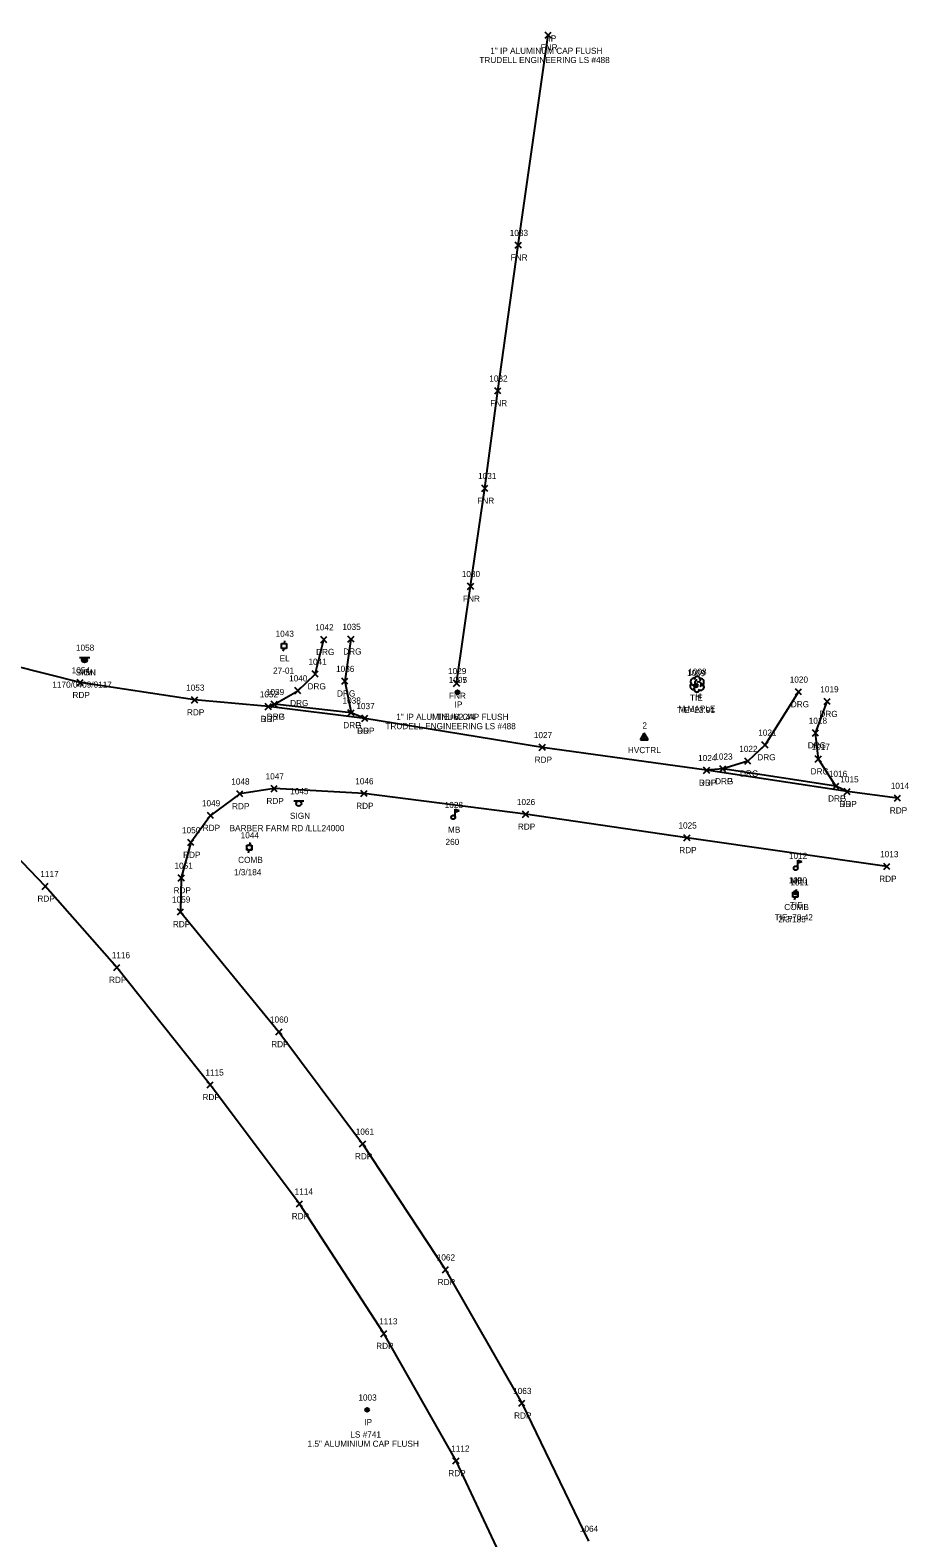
# Model space of a CAD drawing. Extents: x 1503463 to 1505240, y 712171 to 717196.
# Drawn here: x 1504897.3 to 1505182.8, y 713821.7 to 714311.7 of the extents above; entities that cross this region are included whole.
import ezdxf

# ---------------------------------------------------------------- set-up
doc = ezdxf.new("R2010")
doc.units = 0
for name, color, linetype in [('C_A', 7, 'Continuous'), ('C_C', 7, 'Continuous'), ('C_I', 7, 'Continuous'), ('CBP', 7, 'Continuous'), ('CPSM', 7, 'Continuous'), ('L_A', 7, 'Continuous'), ('L_C', 7, 'Continuous'), ('L_I', 7, 'Continuous'), ('L_TIC', 7, 'Continuous'), ('LFNC', 7, 'Continuous'), ('LMB', 7, 'Continuous'), ('LTD', 7, 'Continuous'), ('M_A', 7, 'Continuous'), ('M_C', 7, 'Continuous'), ('M_I', 7, 'Continuous'), ('MPIR', 7, 'Continuous'), ('P_A', 7, 'Continuous'), ('P_I', 7, 'Continuous'), ('P_TIC', 7, 'Continuous'), ('PET', 7, 'Continuous'), ('R_A', 7, 'Continuous'), ('R_I', 7, 'Continuous'), ('R_TIC', 7, 'Continuous'), ('RDG', 7, 'Continuous'), ('RDP', 7, 'Continuous'), ('S_A', 7, 'Continuous'), ('S_C', 7, 'Continuous'), ('S_I', 7, 'Continuous'), ('SRM', 7, 'Continuous'), ('SSGN', 7, 'Continuous'), ('U_A', 7, 'Continuous'), ('U_C', 7, 'Continuous'), ('U_I', 7, 'Continuous'), ('UEPT', 7, 'Continuous'), ('UP', 7, 'Continuous')]:
    doc.layers.add(name, color=color, linetype=linetype)

msp = doc.modelspace()

# ---------------------------------------------------------------- linework, layer by layer
at = {"layer": 'CBP'}
for centre, radius in [((1505113.6, 714098.77), 0.625), ((1505113.6, 714098.77), 0.0833), ((1505146.06, 714031.41), 0.625), ((1505146.06, 714031.41), 0.0833)]:
    msp.add_circle(centre, radius, dxfattribs=at)
at = {"layer": 'CPSM'}
for p, q in [((1505095.56, 714081.03), (1505096.81, 714083.19)), ((1505095.56, 714081.03), (1505096.81, 714081.75)), ((1505095.56, 714081.03), (1505098.06, 714081.03)), ((1505098.06, 714081.03), (1505096.81, 714083.19)), ((1505096.81, 714081.75), (1505096.81, 714083.19)), ((1505096.81, 714081.75), (1505096.81, 714081.75)), ((1505096.81, 714081.75), (1505098.06, 714081.03))]:
    msp.add_line(p, q, dxfattribs=at)
at = {"layer": 'L_TIC'}
for points in [[(1505064.62, 714309.08), (1505066.62, 714311.08)], [(1505066.62, 714309.08), (1505064.62, 714311.08)], [(1505054.9, 714240.8), (1505056.9, 714242.8)], [(1505056.9, 714240.8), (1505054.9, 714242.8)], [(1505048.26, 714193.47), (1505050.26, 714195.47)], [(1505050.26, 714193.47), (1505048.26, 714195.47)], [(1505044.04, 714161.81), (1505046.04, 714163.81)], [(1505046.04, 714161.81), (1505044.04, 714163.81)], [(1505039.41, 714129.96), (1505041.41, 714131.96)], [(1505041.41, 714129.96), (1505039.41, 714131.96)], [(1505034.86, 714098.43), (1505036.86, 714100.43)], [(1505036.86, 714098.43), (1505034.86, 714100.43)]]:
    msp.add_lwpolyline(points, dxfattribs=at)
at = {"layer": 'LFNC'}
msp.add_lwpolyline([(1505035.86, 714099.43), (1505040.41, 714130.96), (1505045.04, 714162.81), (1505049.26, 714194.47), (1505055.9, 714241.8), (1505065.62, 714310.08)], dxfattribs=at)
at = {"layer": 'LMB'}
for p, q in [((1505034.76, 714055.9), (1505034.76, 714055.9)), ((1505035.41, 714058.5), (1505036.7, 714058.12)), ((1505035.41, 714055.91), (1505035.41, 714058.5)), ((1505035.41, 714057.6), (1505036.69, 714058.11)), ((1505146.69, 714041.97), (1505147.98, 714041.58)), ((1505146.7, 714039.37), (1505146.7, 714041.97)), ((1505146.7, 714041.07), (1505147.98, 714041.58)), ((1505146.04, 714039.37), (1505146.04, 714039.37))]:
    msp.add_line(p, q, dxfattribs=at)
for centre in [(1505034.76, 714055.9), (1505146.04, 714039.37)]:
    msp.add_circle(centre, 0.656, dxfattribs=at)
at = {"layer": 'LTD'}
msp.add_line((1505113.98, 714099.22), (1505113.98, 714099.22), dxfattribs=at)
msp.add_line((1505113.98, 714099.22), (1505113.98, 714099.22), dxfattribs=at)
msp.add_arc((1505114.02, 714100.65), 1.05, 335.5272, 180.9563, dxfattribs=at)
for centre, major_axis, ratio, start_param, end_param in [((1505112.89, 714098.51), (0.58, -1.04), 0.959034, 3.141593, 6.283185), ((1505113.18, 714099.89), (1.21, -0.51), 0.895232, 1.570796, 4.712389), ((1505113.77, 714099.68), (-0.208, -0.792), 0.645439, 3.141593, 6.283185), ((1505114.48, 714099.05), (-0.5, 0.667), 0.989748, 3.141593, 6.283185), ((1505114.98, 714098.39), (-1.09, 0.79), 0.841452, 1.570796, 4.712389), ((1505115.02, 714099.8), (-1.14, -0.48), 0.949671, 1.570796, 4.712389), ((1505113.98, 714097.72), (0.26, 1.06), 0.942809, 1.570796, 4.712389), ((1505113.52, 714098.47), (-0.625, -0.083), 0.423636, 0, 3.141593)]:
    msp.add_ellipse(centre, major_axis=major_axis, ratio=ratio, start_param=start_param, end_param=end_param, dxfattribs=at)
at = {"layer": 'MPIR'}
for centre, radius in [((1505036.16, 714096.53), 0.625), ((1505036.17, 714096.54), 0.625), ((1505036.16, 714096.53), 0.0833), ((1505036.17, 714096.54), 0.0833), ((1505006.82, 713863.34), 0.625), ((1505006.82, 713863.34), 0.0833)]:
    msp.add_circle(centre, radius, dxfattribs=at)
at = {"layer": 'P_TIC'}
for points in [[(1504912.58, 714098.65), (1504914.58, 714100.65)], [(1504914.58, 714098.65), (1504912.58, 714100.65)], [(1504949.76, 714093.03), (1504951.76, 714095.03)], [(1504951.76, 714093.03), (1504949.76, 714095.03)], [(1504973.7, 714090.87), (1504975.7, 714092.87)], [(1504975.7, 714090.87), (1504973.7, 714092.87)], [(1505005.07, 714087.04), (1505007.07, 714089.04)], [(1505007.07, 714087.04), (1505005.07, 714089.04)], [(1505062.73, 714077.62), (1505064.73, 714079.62)], [(1505064.73, 714077.62), (1505062.73, 714079.62)], [(1505116.1, 714070.16), (1505118.1, 714072.16)], [(1505118.1, 714070.16), (1505116.1, 714072.16)], [(1504964.42, 714062.52), (1504966.42, 714064.52)], [(1504966.42, 714062.52), (1504964.42, 714064.52)], [(1504975.58, 714064.21), (1504977.58, 714066.21)], [(1504977.58, 714064.21), (1504975.58, 714066.21)], [(1505004.76, 714062.62), (1505006.76, 714064.62)], [(1505006.76, 714062.62), (1505004.76, 714064.62)], [(1505161.73, 714063.23), (1505163.73, 714065.23)], [(1505163.73, 714063.23), (1505161.73, 714065.23)], [(1505178.12, 714061.13), (1505180.12, 714063.13)], [(1505180.12, 714061.13), (1505178.12, 714063.13)], [(1504954.89, 714055.47), (1504956.89, 714057.47)], [(1504956.89, 714055.47), (1504954.89, 714057.47)], [(1505057.28, 714055.87), (1505059.28, 714057.87)], [(1505059.28, 714055.87), (1505057.28, 714057.87)], [(1505109.71, 714048.24), (1505111.71, 714050.24)], [(1505111.71, 714048.24), (1505109.71, 714050.24)], [(1504948.51, 714046.7), (1504950.51, 714048.7)], [(1504950.51, 714046.7), (1504948.51, 714048.7)], [(1505174.67, 714038.92), (1505176.67, 714040.92)], [(1505176.67, 714038.92), (1505174.67, 714040.92)], [(1504945.41, 714035.18), (1504947.41, 714037.18)], [(1504947.41, 714035.18), (1504945.41, 714037.18)], [(1504901.19, 714032.47), (1504903.19, 714034.47)], [(1504903.19, 714032.47), (1504901.19, 714034.47)], [(1504945.19, 714024.17), (1504947.19, 714026.17)], [(1504947.19, 714024.17), (1504945.19, 714026.17)], [(1504924.45, 714006.09), (1504926.45, 714008.09)], [(1504926.45, 714006.09), (1504924.45, 714008.09)], [(1504977.14, 713985.17), (1504979.14, 713987.17)], [(1504979.14, 713985.17), (1504977.14, 713987.17)], [(1504954.82, 713967.98), (1504956.82, 713969.98)], [(1504956.82, 713967.98), (1504954.82, 713969.98)], [(1505004.34, 713948.76), (1505006.34, 713950.76)], [(1505006.34, 713948.76), (1505004.34, 713950.76)], [(1504983.81, 713929.29), (1504985.81, 713931.29)], [(1504985.81, 713929.29), (1504983.81, 713931.29)], [(1505031.24, 713907.87), (1505033.24, 713909.87)], [(1505033.24, 713907.87), (1505031.24, 713909.87)], [(1505011.25, 713887.12), (1505013.25, 713889.12)], [(1505013.25, 713887.12), (1505011.25, 713889.12)], [(1505056.05, 713864.49), (1505058.05, 713866.49)], [(1505058.05, 713864.49), (1505056.05, 713866.49)], [(1505034.67, 713845.75), (1505036.67, 713847.75)], [(1505036.67, 713845.75), (1505034.67, 713847.75)]]:
    msp.add_lwpolyline(points, dxfattribs=at)
at = {"layer": 'PET'}
for points in [[(1505179.12, 714062.13), (1505162.73, 714064.23), (1505117.1, 714071.16), (1505063.73, 714078.62), (1505006.07, 714088.04), (1504974.7, 714091.87), (1504950.76, 714094.03), (1504913.58, 714099.65), (1504891.67, 714105.18), (1504874.38, 714111.13), (1504858.75, 714121.03), (1504839.76, 714141.64), (1504813.09, 714174.5), (1504792.31, 714203.38), (1504770.85, 714238.46), (1504747.85, 714282.15), (1504727.38, 714327.5), (1504712.05, 714367.82), (1504697.71, 714414.83), (1504685.11, 714458.97), (1504676.94, 714491.61), (1504665.42, 714541.32), (1504657.14, 714577.6), (1504649.31, 714613.48)], [(1505055.48, 713804.69), (1505035.67, 713846.75), (1505012.25, 713888.12), (1504984.81, 713930.29), (1504955.82, 713968.98), (1504925.45, 714007.09), (1504902.19, 714033.47), (1504875.2, 714061.56), (1504841.23, 714097.76), (1504824.92, 714116.29), (1504805.14, 714139.73), (1504789.93, 714158.37), (1504770.9, 714185.14), (1504747.1, 714223.61), (1504721.17, 714273.06), (1504701.58, 714317.3), (1504686.12, 714357.97), (1504670.15, 714407.6), (1504658, 714450.85), (1504649.24, 714485.62), (1504637.84, 714534.39), (1504628.86, 714571.69), (1504621.33, 714603.22)], [(1505175.67, 714039.92), (1505110.71, 714049.24), (1505058.28, 714056.87), (1505005.76, 714063.62), (1504976.58, 714065.21), (1504965.42, 714063.52), (1504955.89, 714056.47), (1504949.51, 714047.7), (1504946.41, 714036.18), (1504946.19, 714025.17), (1504978.14, 713986.17), (1505005.34, 713949.76), (1505032.24, 713908.87), (1505057.05, 713865.49), (1505078.73, 713820.71)]]:
    msp.add_lwpolyline(points, dxfattribs=at)
at = {"layer": 'R_TIC'}
for points in [[(1504991.72, 714112.64), (1504993.72, 714114.64)], [(1504993.72, 714112.64), (1504991.72, 714114.64)], [(1505000.54, 714112.78), (1505002.54, 714114.78)], [(1505002.54, 714112.78), (1505000.54, 714114.78)], [(1504988.94, 714101.45), (1504990.94, 714103.45)], [(1504990.94, 714101.45), (1504988.94, 714103.45)], [(1504998.54, 714099.14), (1505000.54, 714101.14)], [(1505000.54, 714099.14), (1504998.54, 714101.14)], [(1504983.3, 714096.04), (1504985.3, 714098.04)], [(1504985.3, 714096.04), (1504983.3, 714098.04)], [(1505145.95, 714095.65), (1505147.95, 714097.65)], [(1505147.95, 714095.65), (1505145.95, 714097.65)], [(1505155.24, 714092.5), (1505157.24, 714094.5)], [(1505157.24, 714092.5), (1505155.24, 714094.5)], [(1504973.7, 714090.87), (1504975.7, 714092.87)], [(1504975.7, 714090.87), (1504973.7, 714092.87)], [(1504975.67, 714091.61), (1504977.67, 714093.61)], [(1504977.67, 714091.61), (1504975.67, 714093.61)], [(1504975.67, 714091.61), (1504977.67, 714093.61)], [(1504977.67, 714091.61), (1504975.67, 714093.61)], [(1505000.57, 714088.84), (1505002.57, 714090.84)], [(1505002.57, 714088.84), (1505000.57, 714090.84)], [(1505000.57, 714088.84), (1505002.57, 714090.84)], [(1505002.57, 714088.84), (1505000.57, 714090.84)], [(1505005.07, 714087.04), (1505007.07, 714089.04)], [(1505007.07, 714087.04), (1505005.07, 714089.04)], [(1505151.47, 714082.29), (1505153.47, 714084.29)], [(1505153.47, 714082.29), (1505151.47, 714084.29)], [(1505135.07, 714078.41), (1505137.07, 714080.41)], [(1505137.07, 714078.41), (1505135.07, 714080.41)], [(1505129.46, 714073.13), (1505131.46, 714075.13)], [(1505131.46, 714073.13), (1505129.46, 714075.13)], [(1505152.4, 714073.82), (1505154.4, 714075.82)], [(1505154.4, 714073.82), (1505152.4, 714075.82)], [(1505116.1, 714070.16), (1505118.1, 714072.16)], [(1505118.1, 714070.16), (1505116.1, 714072.16)], [(1505121.36, 714070.64), (1505123.36, 714072.64)], [(1505123.36, 714070.64), (1505121.36, 714072.64)], [(1505121.36, 714070.64), (1505123.36, 714072.64)], [(1505123.36, 714070.64), (1505121.36, 714072.64)], [(1505158.06, 714065.02), (1505160.06, 714067.02)], [(1505160.06, 714065.02), (1505158.06, 714067.02)], [(1505158.06, 714065.02), (1505160.06, 714067.02)], [(1505160.06, 714065.02), (1505158.06, 714067.02)], [(1505161.73, 714063.23), (1505163.73, 714065.23)], [(1505163.73, 714063.23), (1505161.73, 714065.23)]]:
    msp.add_lwpolyline(points, dxfattribs=at)
at = {"layer": 'RDG'}
for points in [[(1504976.67, 714092.61), (1504984.3, 714097.04), (1504989.94, 714102.45), (1504992.72, 714113.64)], [(1505001.54, 714113.78), (1504999.54, 714100.14), (1505001.57, 714089.84)], [(1505146.95, 714096.65), (1505136.07, 714079.41), (1505130.46, 714074.13), (1505122.36, 714071.64)], [(1505159.06, 714066.02), (1505153.4, 714074.82), (1505152.47, 714083.29), (1505156.24, 714093.5)]]:
    msp.add_lwpolyline(points, dxfattribs=at)
at = {"layer": 'RDP'}
for points in [[(1505006.07, 714088.04), (1505001.57, 714089.84), (1504976.67, 714092.61), (1504974.7, 714091.87)], [(1505162.73, 714064.23), (1505159.06, 714066.02), (1505122.36, 714071.64), (1505117.1, 714071.16)]]:
    msp.add_lwpolyline(points, dxfattribs=at)
at = {"layer": 'SRM'}
msp.add_lwpolyline([(1504914.34, 714107.65), (1504915.59, 714107.65), (1504915.59, 714106.4), (1504914.34, 714106.4)], close=True, dxfattribs=at)
msp.add_circle((1504914.97, 714107.02), 0.0833, dxfattribs=at)
at = {"layer": 'SSGN'}
for p, q in [((1504913.34, 714107.88), (1504916.67, 714107.88)), ((1504914.98, 714107.04), (1504914.98, 714107.04)), ((1504982.95, 714061.23), (1504986.28, 714061.23)), ((1504984.59, 714060.4), (1504984.59, 714060.4))]:
    msp.add_line(p, q, dxfattribs=at)
for centre in [(1504914.98, 714107.04), (1504984.59, 714060.4)]:
    msp.add_circle(centre, 0.833, dxfattribs=at)
at = {"layer": 'UEPT'}
for p, q in [((1504978.98, 714110.73), (1504978.98, 714112.4)), ((1504978.98, 714112.4), (1504980.65, 714112.4)), ((1504980.65, 714110.73), (1504978.98, 714110.73)), ((1504979.57, 714109.9), (1504979.82, 714110.73)), ((1504979.98, 714113.23), (1504979.82, 714112.4)), ((1504979.82, 714111.56), (1504979.82, 714111.56)), ((1504980.65, 714112.4), (1504980.65, 714110.73))]:
    msp.add_line(p, q, dxfattribs=at)
at = {"layer": 'UP'}
for p, q in [((1504967.66, 714045.23), (1504967.66, 714046.89)), ((1504967.66, 714046.89), (1504969.33, 714046.89)), ((1504969.33, 714045.23), (1504967.66, 714045.23)), ((1504968.25, 714044.39), (1504968.5, 714045.23)), ((1504968.75, 714047.73), (1504968.5, 714046.89)), ((1504968.5, 714046.06), (1504968.5, 714046.06)), ((1504969.33, 714046.89), (1504969.33, 714045.23)), ((1505145.09, 714029.91), (1505145.09, 714031.57)), ((1505145.09, 714031.57), (1505146.76, 714031.57)), ((1505146.17, 714032.41), (1505145.92, 714031.57)), ((1505145.92, 714030.74), (1505145.92, 714030.74)), ((1505146.76, 714031.57), (1505146.76, 714029.91)), ((1505146.76, 714029.91), (1505145.09, 714029.91)), ((1505145.67, 714029.07), (1505145.92, 714029.91))]:
    msp.add_line(p, q, dxfattribs=at)
for centre in [(1504968.5, 714046.06), (1505145.92, 714030.74)]:
    msp.add_circle(centre, 0.833, dxfattribs=at)

# ---------------------------------------------------------------- texts
at = {"layer": 'C_A'}
for s, p in [('TIE', (1505111.68, 714093.77)), ('HVCTRL', (1505091.5, 714076.75)), ('TIE', (1505144.14, 714026.41))]:
    msp.add_text(s, height=2, dxfattribs=at).set_placement(p)
at = {"layer": 'C_C'}
for s, p in [('TIE=23.91', (1505107.4, 714089.77)), ('TIE=70.42', (1505139.21, 714022.41))]:
    msp.add_text(s, height=2, dxfattribs=at).set_placement(p)
at = {"layer": 'C_I'}
for s, p in [('1009', (1505110.74, 714101.77)), ('2', (1505096.24, 714084.75)), ('1010', (1505143.77, 714034.41))]:
    msp.add_text(s, height=2, dxfattribs=at).set_placement(p)
at = {"layer": 'L_A'}
for s, p in [('FNR', (1505063.16, 714305.08)), ('FNR', (1505053.43, 714236.8)), ('FNR', (1505046.79, 714189.47)), ('FNR', (1505042.58, 714157.81)), ('FNR', (1505037.95, 714125.96)), ('FNR', (1505033.4, 714094.43)), ('H', (1505113.41, 714094.22)), ('MB', (1505033.06, 714050.9)), ('MB', (1505144.35, 714034.37))]:
    msp.add_text(s, height=2, dxfattribs=at).set_placement(p)
at = {"layer": 'L_C'}
for s, p in [('M.MAPLE', (1505107.91, 714090.22)), ('260', (1505032.26, 714046.9))]:
    msp.add_text(s, height=2, dxfattribs=at).set_placement(p)
at = {"layer": 'L_I'}
for s, p in [('1033', (1505053.13, 714244.8)), ('1032', (1505046.48, 714197.47)), ('1031', (1505042.84, 714165.81)), ('1030', (1505037.55, 714133.96)), ('1029', (1505033.08, 714102.43)), ('1008', (1505111.13, 714102.22)), ('1028', (1505031.99, 714058.9)), ('1012', (1505143.84, 714042.37))]:
    msp.add_text(s, height=2, dxfattribs=at).set_placement(p)
at = {"layer": 'M_A'}
for p in [(1505065.73, 714307.99), (1505035.21, 714091.53), (1505035.22, 714091.54), (1505005.86, 713858.34)]:
    msp.add_text('IP', height=2, dxfattribs=at).set_placement(p)
at = {"layer": 'M_C'}
for s, p in [('1" IP ALUMINUM CAP FLUSH', (1505046.79, 714303.99)), ('TRUDELL ENGINEERING LS #488', (1505043.25, 714300.99)), ('1" IP ALUMINUM CAP FLUSH', (1505016.27, 714087.53)), ('TIE=62.44', (1505029.36, 714087.54)), ('TRUDELL ENGINEERING LS #488', (1505012.73, 714084.53)), ('LS #741', (1505001.34, 713854.34)), ('1.5" ALUMINIUM CAP FLUSH', (1504987.43, 713851.34))]:
    msp.add_text(s, height=2, dxfattribs=at).set_placement(p)
at = {"layer": 'M_I'}
for s, p in [('1005', (1505033.31, 714099.53)), ('1007', (1505033.32, 714099.54)), ('1003', (1505003.96, 713866.34))]:
    msp.add_text(s, height=2, dxfattribs=at).set_placement(p)
at = {"layer": 'P_A'}
for p in [(1504911.07, 714094.65), (1504948.25, 714089.03), (1504972.19, 714086.87), (1505003.55, 714083.04), (1505061.22, 714073.62), (1505114.58, 714066.16), (1504962.91, 714058.52), (1504974.07, 714060.21), (1505003.24, 714058.62), (1505160.22, 714059.23), (1505176.61, 714057.13), (1504953.38, 714051.47), (1505055.77, 714051.87), (1505108.2, 714044.24), (1504947, 714042.7), (1505173.16, 714034.92), (1504899.68, 714028.47), (1504943.9, 714031.18), (1504943.68, 714020.17), (1504922.93, 714002.09), (1504975.63, 713981.17), (1504953.31, 713963.98), (1505002.83, 713944.76), (1504982.3, 713925.29), (1505029.73, 713903.87), (1505009.74, 713883.12), (1505054.54, 713860.49), (1505033.16, 713841.75)]:
    msp.add_text('RDP', height=2, dxfattribs=at).set_placement(p)
at = {"layer": 'P_I'}
for s, p in [('1054', (1504910.81, 714102.65)), ('1053', (1504947.99, 714097.03)), ('1052', (1504971.93, 714094.87)), ('1037', (1505003.3, 714091.04)), ('1027', (1505060.96, 714081.62)), ('1024', (1505114.32, 714074.16)), ('1047', (1504973.81, 714068.21)), ('1048', (1504962.65, 714066.52)), ('1046', (1505002.93, 714066.62)), ('1015', (1505160.53, 714067.23)), ('1014', (1505176.92, 714065.13)), ('1049', (1504953.11, 714059.47)), ('1026', (1505055.45, 714059.87)), ('1050', (1504946.65, 714050.7)), ('1025', (1505107.94, 714052.24)), ('1013', (1505173.46, 714042.92)), ('1051', (1504944.21, 714039.18)), ('1117', (1504900.63, 714036.47)), ('1059', (1504943.41, 714028.17)), ('1116', (1504923.83, 714010.09)), ('1060', (1504975.24, 713989.17)), ('1115', (1504954.26, 713971.98)), ('1061', (1505003.09, 713952.76)), ('1114', (1504983.25, 713933.29)), ('1062', (1505029.42, 713911.87)), ('1113', (1505010.69, 713891.12)), ('1063', (1505054.23, 713868.49)), ('1112', (1505034.11, 713849.75)), ('1064', (1505075.91, 713823.71))]:
    msp.add_text(s, height=2, dxfattribs=at).set_placement(p)
at = {"layer": 'R_A'}
for s, p in [('DRG', (1504990.21, 714108.64)), ('DRG', (1504999.03, 714108.78)), ('DRG', (1504987.43, 714097.45)), ('DRG', (1504981.78, 714092.04)), ('DRG', (1504997.02, 714095.14)), ('DRG', (1504974.16, 714087.61)), ('DRP', (1504974.16, 714087.61)), ('DRG', (1505144.44, 714091.65)), ('DRG', (1505153.73, 714088.5)), ('DRP', (1504972.19, 714086.87)), ('DRG', (1504999.06, 714084.84)), ('DRP', (1504999.06, 714084.84)), ('DRP', (1505003.55, 714083.04)), ('DRG', (1505149.96, 714078.29)), ('DRG', (1505133.56, 714074.41)), ('DRG', (1505127.95, 714069.13)), ('DRG', (1505150.88, 714069.82)), ('DRP', (1505114.58, 714066.16)), ('DRG', (1505119.85, 714066.64)), ('DRP', (1505119.85, 714066.64)), ('DRG', (1505156.55, 714061.02)), ('DRP', (1505156.55, 714061.02)), ('DRP', (1505160.22, 714059.23))]:
    msp.add_text(s, height=2, dxfattribs=at).set_placement(p)
at = {"layer": 'R_I'}
for s, p in [('1042', (1504989.95, 714116.64)), ('1035', (1504998.77, 714116.78)), ('1041', (1504987.73, 714105.45)), ('1036', (1504996.71, 714103.14)), ('1040', (1504981.44, 714100.04)), ('1020', (1505144.09, 714099.65)), ('1052', (1504971.93, 714094.87)), ('1039', (1504973.89, 714095.61)), ('1039', (1504973.89, 714095.61)), ('1038', (1504998.8, 714092.84)), ('1038', (1504998.8, 714092.84)), ('1019', (1505154.03, 714096.5)), ('1037', (1505003.3, 714091.04)), ('1021', (1505133.86, 714082.41)), ('1018', (1505150.26, 714086.29)), ('1017', (1505151.19, 714077.82)), ('1024', (1505114.32, 714074.16)), ('1023', (1505119.59, 714074.64)), ('1023', (1505119.59, 714074.64)), ('1022', (1505127.69, 714077.13)), ('1016', (1505156.8, 714069.02)), ('1016', (1505156.8, 714069.02)), ('1015', (1505160.53, 714067.23))]:
    msp.add_text(s, height=2, dxfattribs=at).set_placement(p)
at = {"layer": 'S_A'}
for s, p in [('SIGN', (1504912.12, 714102.02)), ('MM', (1504913.15, 714102.02)), ('SIGN', (1504981.73, 714055.38))]:
    msp.add_text(s, height=2, dxfattribs=at).set_placement(p)
at = {"layer": 'S_C'}
for s, p in [('1170/0409/0117', (1504904.53, 714098.02)), ('BARBER FARM RD /LLL24000', (1504962.11, 714051.38))]:
    msp.add_text(s, height=2, dxfattribs=at).set_placement(p)
at = {"layer": 'S_I'}
for s, p in [('1058', (1504912.19, 714110.02)), ('1058', (1504912.19, 714110.02)), ('1045', (1504981.8, 714063.38))]:
    msp.add_text(s, height=2, dxfattribs=at).set_placement(p)
at = {"layer": 'U_A'}
for s, p in [('EL', (1504978.35, 714106.56)), ('COMB', (1504964.88, 714041.06)), ('COMB', (1505142.31, 714025.74))]:
    msp.add_text(s, height=2, dxfattribs=at).set_placement(p)
at = {"layer": 'U_C'}
for s, p in [('27-01', (1504976.23, 714102.56)), ('1/3/184', (1504963.52, 714037.06)), ('2/3/185', (1505140.38, 714021.74))]:
    msp.add_text(s, height=2, dxfattribs=at).set_placement(p)
at = {"layer": 'U_I'}
for s, p in [('1043', (1504977.05, 714114.56)), ('1044', (1504965.72, 714049.06)), ('1011', (1505144.29, 714033.74))]:
    msp.add_text(s, height=2, dxfattribs=at).set_placement(p)

doc.saveas('drawing.dxf')
